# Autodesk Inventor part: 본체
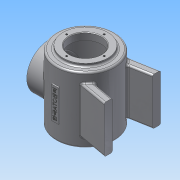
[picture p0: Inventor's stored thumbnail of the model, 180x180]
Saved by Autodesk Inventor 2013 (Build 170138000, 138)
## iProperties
Created: 2015-01
Part Number: 본체
Material: 알루미늄 6061
Document SubType Name: Modeling
Designer: Administrator
Density: 2.71089 g/cm^3
Mass: 1022 g
Surface Area: 1060.64 cm^2
Volume: 376.997 cm^3
Author: Administrator
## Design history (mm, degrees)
sketch "스케치1"
  geometry: C1 r 50 at (0, 0); 1 further point
  constraints: 1 centre point, 1 coincident
  dimensions: "d0" = 100 diameter of C1
extrude "돌출1" new body sketch "스케치1" stored distance "d1" = 112; taper "d2" = 0 deg
sketch "스케치2"
  geometry: C1 r 38 at (0, 0); 1 further point
  constraints: 1 centre point, 1 coincident
  dimensions: "d3" = 76 diameter of C1
extrude "돌출2" join sketch "스케치2" distance "d4" = 5; taper "d5" = 0 deg
sketch "스케치4"
  geometry: L1 (0, -48.5)-(45, -48.5); L2 (45, -48.5)-(45, 48.5); L3 (45, 48.5)-(0, 48.5); L4 (0, 48.5)-(0, -48.5); 2 further points
  constraints: 8 end point, 2 parallel, 1 coincident, 1 horizontal, 1 midpoint, 1 perpendicular
  dimensions: "d6" = 97 distance of L1.end L2.end; "d8" = 90 diameter of L2 L4
sketch "스케치6"
  geometry: C1 r 27 at (0, 0); 1 further point
  constraints: 1 centre point, 1 coincident
  dimensions: "d10" = 54 diameter of C1
extrude "돌출3" cut sketch "스케치6" stored distance "d11" = 5; taper "d12" = 0 deg
node "작업 평면1"
sketch "스케치7"
  geometry: C1 r 38 at (0, 0); 1 further point
  constraints: 1 centre point, 1 coincident
  dimensions: "d14" = 76 diameter of C1
extrude "돌출4" join sketch "스케치7" stored distance "d15" = 5; taper "d16" = 0 deg
sketch "스케치8"
  geometry: C1 r 27 at (0, 0); 1 further point
  constraints: 1 centre point, 1 coincident
  dimensions: "d17" = 54 diameter of C1
extrude "돌출5" cut sketch "스케치8" stored distance "d18" = 5; taper "d19" = 0 deg
sketch "스케치9"
  geometry: 2 further points
  constraints: 1 vertical alignment
  dimensions: "d20" = 32 distance of point (0, 0) point (0, 32)
hole "구멍1" sketch "스케치9" at (0, 32) diameter "d21" = 3.242; stored, may be unused: countersink angle "d25" = 90 deg, drill point angle "d27" = 118 deg; dims "d22" = 8, "d23" = 4, "d24" = 2, "d26" = 10
sketch "스케치10"
  geometry: 2 further points
  constraints: 1 vertical alignment
  dimensions: "d31" = 32 distance of point (0, 32) point (0, 0)
hole "구멍2" sketch "스케치10" at (0, 32) diameter "d32" = 3.242; stored, may be unused: countersink angle "d36" = 90 deg, drill point angle "d38" = 118 deg; dims "d33" = 8, "d34" = 4, "d35" = 2, "d37" = 10
node "작업 평면3"
sketch "스케치11"
  geometry: L1 (-32.496, -38)-(-62, -38) reference; L2 (-62, -38)-(-62, -33.621) reference; L3 (-62, -33.621)-(-52, -33.621) reference; L4 (-52, -33.621)-(-51.026, -32) reference; L5 (-51.026, -32)-(-52, -30.379) reference; L6 (-52, -30.379)-(-62, -30.379) reference; L7 (-62, -30.379)-(-62, -27) reference; L8 (-62, -27)-(0, -27) reference; L9 (0, 27)-(-62, 27) reference; L10 (-62, 27)-(-62, 30.379) reference; L11 (-62, 30.379)-(-52, 30.379) reference; L12 (-52, 30.379)-(-51.026, 32) reference; L13 (-51.026, 32)-(-52, 33.621) reference; L14 (-52, 33.621)-(-62, 33.621) reference; L15 (-62, 33.621)-(-62, 38) reference; L16 (-62, 38)-(-32.496, 38) reference; L17 (80, 34.111)-(80, 48.111); L18 (80, 48.111)-(30.75, 39.427); L19 (80, 34.111)-(41.836, 27.381); A1 r 50 centre (0, 0) between (-32.496, -38) and (-32.496, 38) reference; A2 r 27 centre (0, 0) between (0, -27) and (0, 27) reference; 1 further point
  constraints: 6 end point, 2 point on circle, 1 parallel, 1 perpendicular
  dimensions: "d49" = 80 horizontal distance of L17.end point (0, 0); "d50" = 100 deg angle of L18 L17; "d53" = 14 distance of L17.start L17.end; "d54" = 38.16387 horizontal distance of L17.start L19.end
extrude "돌출6" join sketch "스케치11" stored distance "d55" = 80; taper "d56" = 0 deg
node "작업 평면4"
fillet "모깎기1" dims "d66" = 3
fillet "모깎기2" dims "d67" = 3
chamfer "모따기1" distance "d68" = 1; stored, may be unused: second distance "d69" = 2, angle "d70" = 45 deg
node "작업 평면6"
node "작업 평면7"
sketch "스케치16"
  geometry: L1 (6, -27)-(-6, -27); L2 (-6, -27)-(-6, 27); L3 (-6, 27)-(6, 27); L4 (6, 27)-(6, -27); L5 (6, -27)-(-6, 27); L6 (-6, -27)-(6, 27); 1 further point
  constraints: 12 end point, 2 midpoint, 2 parallel, 1 horizontal, 1 perpendicular
  dimensions: "d85" = 12 distance of L2.end L3.end; "d86" = 54 distance of L1.end L2.end
extrude "돌출8" join sketch "스케치16" stored distance "d87" = 10; taper "d88" = 0 deg
sketch "스케치17"
  geometry: L1 (38, -61)-(-38, -61) reference; 2 further points
  constraints: 2 coincident, 1 other
feature "엠보싱5" sketch "스케치17" dims "d90" = 0.5, "d91" = 0
node "작업 평면9"
sketch "스케치19"
  geometry: C1 r 45 at (0, 0); 1 further point
  constraints: 1 centre point, 1 coincident
  dimensions: "d98" = 90 diameter of C1
extrude "돌출10" cut sketch "스케치19" distance "d99" = 97; taper "d100" = 0 deg
fillet "모깎기5" dims "d101" = 3
node "솔리드1"
mirror "대칭1"
pattern_circular "원형 패턴1" dims angle "d29" = 360 deg
pattern_circular "원형 패턴2" dims angle "d40" = 360 deg
mirror "대칭2"
mirror "대칭3"
node "절단 모서리 투영1"
other parameters: "d13" = -62, "d84" = -2, "d97" = -12
